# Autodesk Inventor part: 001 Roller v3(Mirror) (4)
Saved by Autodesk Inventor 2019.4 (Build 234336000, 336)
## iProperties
Created: 2020-06
Part Number: 001 Roller v3(Mirror) (4)
Material: Generic
Document SubType Name: Modeling
Designer: Administrator
Density: 1 g/cm^3
Appearance: Default
Title: 001 Roller v3(Mirror) (4)
Author: Administrator
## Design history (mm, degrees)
